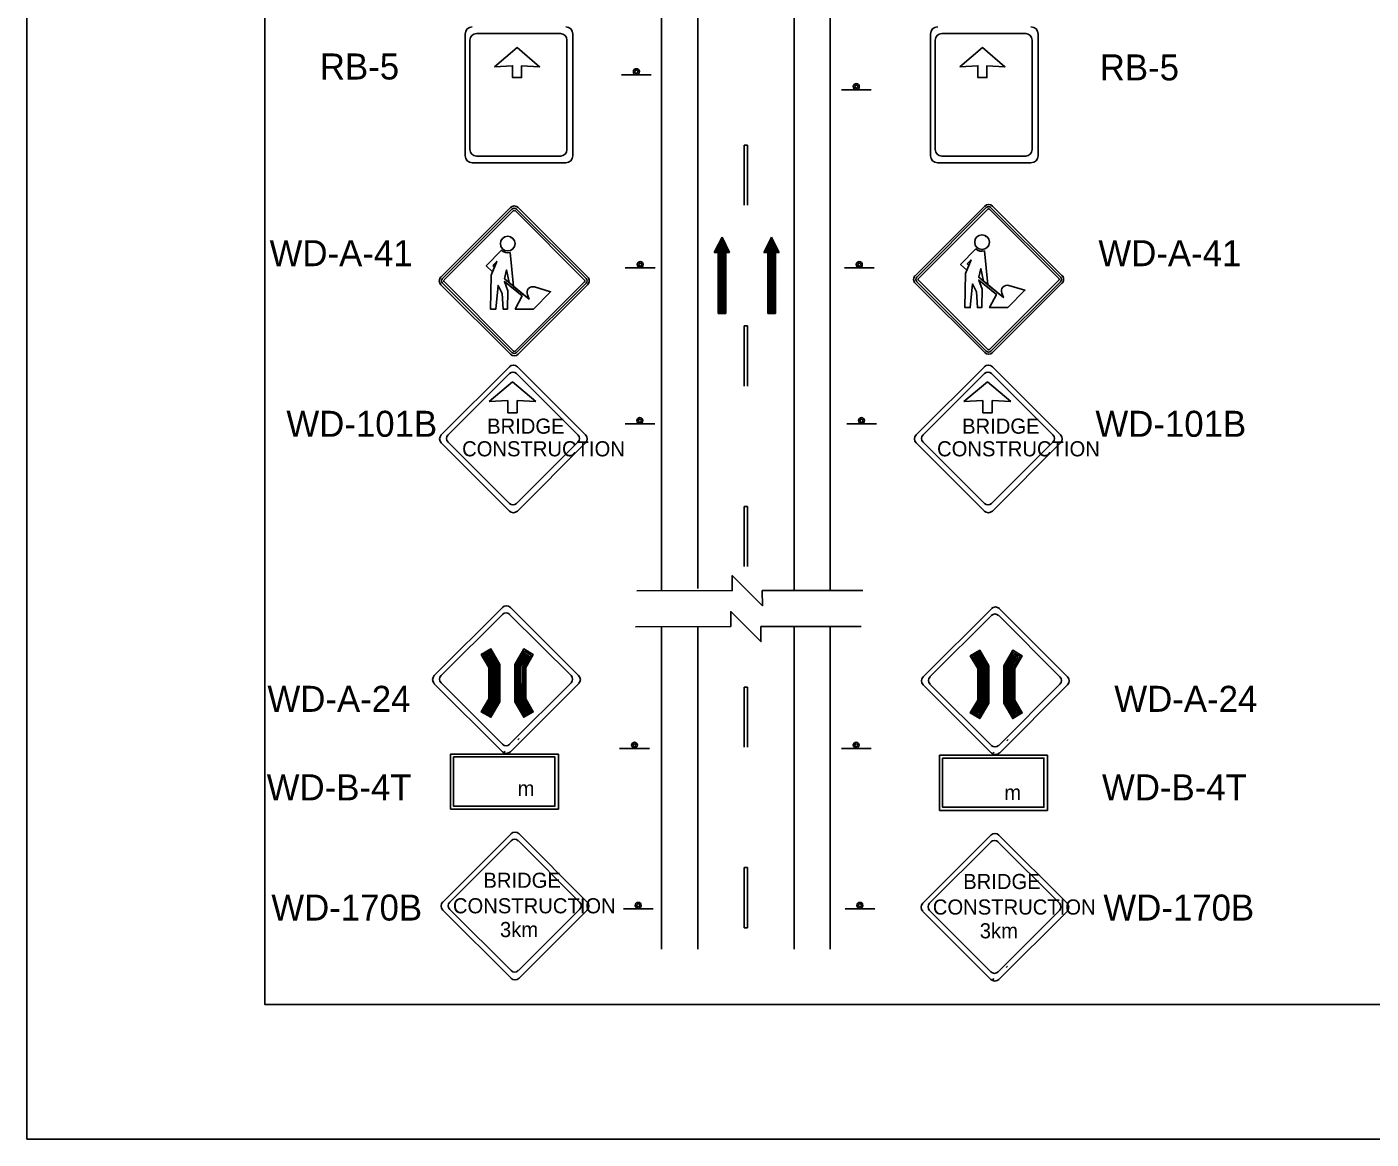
# Model space of a CAD drawing. Extents: x 2170 to 2386, y 134 to 413.
# Drawn here: x 2169.6 to 2277.6, y 133.8 to 223.1 of the extents above; entities that cross this region are included whole.
import ezdxf

# ---------------------------------------------------------------- set-up
doc = ezdxf.new("R2010")
doc.units = 0
for name, color, linetype in [('Level 1', 7, 'Continuous'), ('Level 10', 7, 'Continuous'), ('Level 2', 7, 'Continuous'), ('Level 20', 7, 'Continuous'), ('Level 44', 7, 'Continuous'), ('Level 60', 7, 'Continuous')]:
    doc.layers.add(name, color=color, linetype=linetype)

# ---------------------------------------------------------------- blocks, each defined once
blk = doc.blocks.new('2_95')
at = {"layer": 'Level 1'}
for points in [[(18.2, 120), (22.8, 116.1), (17.3, 102.4), (0, 118.7), (41.6, 161.6)], [(18.2, 120), (22.8, 116.1), (17.3, 102.4), (0, 118.7), (41.6, 161.6)], [(32.4, 65), (26.3, 0), (11.7, 0), (13.7, 93.4), (17.3, 102.4), (0, 118.7), (41.6, 161.6)], [(65.4, 155.5), (75, 62.5), (62.7, 72.8), (55.6, 107.4), (49.8, 83.3), (117.8, 27.3), (113.1, 39.4)], [(65.4, 155.5), (75, 62.5), (62.7, 72.8), (55.6, 107.4), (49.8, 83.3), (117.8, 27.3), (113.1, 39.4)], [(65.4, 155.5), (75, 62.5), (117.8, 27.3), (113.1, 39.4)], [(132.9, 60.9), (176.6, 47.8), (129.3, 0), (79.5, 0), (98.2, 36), (49.8, 75.6), (59.3, 50.4), (58.1, 0), (46.2, 0), (44, 43), (32.4, 65), (26.3, 0), (11.7, 0), (13.7, 93.4), (28.7, 130.9), (18.2, 120)], [(132.9, 60.9), (176.6, 47.8), (129.3, 0), (79.5, 0), (98.2, 36), (49.8, 75.6), (59.3, 50.4), (58.1, 0), (46.2, 0), (44, 43), (32.4, 65), (26.3, 0), (11.7, 0), (13.7, 93.4), (28.7, 130.9), (18.2, 120)], [(132.9, 60.9), (176.6, 47.8), (129.3, 0), (79.5, 0), (98.2, 36), (49.8, 75.6), (59.3, 50.4), (58.1, 0), (46.2, 0), (44, 43), (32.4, 65)]]:
    blk.add_lwpolyline(points, dxfattribs=at)
for points in [[(18.2, 120), (22.8, 116.1), (28.7, 130.9)], [(62.7, 72.7), (55.6, 107.4), (49.8, 83.3)]]:
    blk.add_lwpolyline(points, close=True, dxfattribs=at)
blk.add_circle((58.9, 179.8), 20.2, dxfattribs=at)
blk.add_circle((58.9, 179.8), 20.2, dxfattribs=at)
blk.add_circle((58.9, 179.8), 20.2, dxfattribs=at)
for centre, radius, start, end in [((58.9, 179.8), 25.1, 226.3135, 284.9576), ((58.9, 179.8), 25.1, 226.3135, 284.9576), ((58.9, 179.8), 25.1, 226.3135, 284.9576), ((128.2, 45.3), 16.3, 73.381, 201.0999), ((128.2, 45.3), 16.3, 73.381, 201.0999), ((128.2, 45.3), 16.3, 73.381, 201.0999)]:
    blk.add_arc(centre, radius, start, end, dxfattribs=at)
blk = doc.blocks.new('WDA41')
at = {"layer": 'Level 1'}
for p, q in [((-6.55, 0.35), (-0.35, 6.54)), ((-6.41, 0.21), (-0.21, 6.4)), ((-6.27, 0.07), (-0.08, 6.27)), ((0.07, 6.27), (6.27, 0.08)), ((0.21, 6.41), (6.41, 0.21)), ((0.35, 6.54), (6.54, 0.35)), ((0.29, 3.83), (0.3, 3.83)), ((-0.35, -6.54), (-6.55, -0.35)), ((-0.21, -6.4), (-6.41, -0.21)), ((-0.07, -6.27), (-6.27, -0.08)), ((6.27, -0.07), (0.08, -6.27)), ((6.41, -0.21), (0.21, -6.4)), ((6.55, -0.35), (0.35, -6.54))]:
    blk.add_line(p, q, dxfattribs=at)
for centre, radius, start, end in [((0, 6.19), 0.495, 45.0349, 135), ((0, 6.19), 0.3, 45.0349, 135), ((0, 6.19), 0.105, 45.0349, 135), ((-6.2, 0), 0.495, 135, 225.0349), ((-6.2, 0), 0.3, 135, 225.0349), ((-6.2, 0), 0.105, 135, 225.0349), ((6.2, 0), 0.105, 315, 45.035), ((6.2, 0), 0.3, 315, 45.035), ((6.2, 0), 0.495, 315, 45.035), ((0, -6.19), 0.495, 225.0348, 315), ((0, -6.19), 0.3, 225.0348, 315), ((0, -6.19), 0.105, 225.0348, 315)]:
    blk.add_arc(centre, radius, start, end, dxfattribs=at)
at = {"layer": 'Level 1', "xscale": 0.032498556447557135, "yscale": -0.032498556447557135, "rotation": 180}
blk.add_blockref('2_95', (2.5, -2.52), dxfattribs=at)

msp = doc.modelspace()

# ---------------------------------------------------------------- linework, layer by layer
at = {"layer": 'Level 10'}
for p, q in [((2223.52, 177.99), (2223.52, 287.5)), ((2231.26, 177.84), (2231.26, 287.27)), ((2225.47, 206.23), (2224.85, 205)), ((2225.01, 205.31), (2225.01, 205)), ((2225.08, 205.46), (2225.08, 205)), ((2225.16, 205.62), (2225.16, 200.09)), ((2225.24, 205.77), (2225.24, 200.09)), ((2225.31, 205.92), (2225.31, 200.09)), ((2225.39, 206.08), (2225.39, 200.09)), ((2225.47, 206.23), (2225.47, 200.09)), ((2225.47, 206.23), (2226.08, 205)), ((2225.54, 206.08), (2225.54, 200.09)), ((2225.62, 205.92), (2225.62, 200.09)), ((2225.7, 205.77), (2225.7, 200.09)), ((2225.77, 205.62), (2225.77, 200.09)), ((2225.85, 205.46), (2225.85, 205)), ((2225.93, 205.31), (2225.93, 205)), ((2229.45, 206.23), (2228.84, 205)), ((2228.99, 205.31), (2228.99, 205)), ((2229.07, 205.46), (2229.07, 205)), ((2229.14, 205.62), (2229.14, 200.09)), ((2229.22, 205.77), (2229.22, 200.09)), ((2229.3, 205.92), (2229.3, 200.09)), ((2229.38, 206.08), (2229.38, 200.09)), ((2229.45, 206.23), (2229.45, 200.09)), ((2229.45, 206.23), (2230.06, 205)), ((2229.53, 206.08), (2229.53, 200.09)), ((2229.6, 205.92), (2229.6, 200.09)), ((2229.68, 205.77), (2229.68, 200.09)), ((2229.76, 205.62), (2229.76, 200.09)), ((2229.83, 205.46), (2229.83, 205)), ((2229.91, 205.31), (2229.91, 205)), ((2224.85, 205), (2225.16, 205)), ((2224.93, 205.16), (2224.93, 205)), ((2225.16, 205), (2225.16, 200.09)), ((2225.77, 205), (2225.77, 200.09)), ((2225.77, 205), (2226.08, 205)), ((2226, 205.16), (2226, 205)), ((2228.84, 205), (2229.14, 205)), ((2228.91, 205.16), (2228.91, 205)), ((2229.14, 205), (2229.14, 200.09)), ((2229.76, 205), (2229.76, 200.09)), ((2229.76, 205), (2230.06, 205)), ((2229.99, 205.16), (2229.99, 205)), ((2225.16, 200.09), (2225.77, 200.09)), ((2229.14, 200.09), (2229.76, 200.09)), ((2223.52, 149.02), (2223.52, 174.93)), ((2231.26, 149.02), (2231.26, 174.95))]:
    msp.add_line(p, q, dxfattribs=at)
for points in [[(2203.91, 164.47), (2212.05, 164.47), (2212.05, 160.51), (2203.91, 160.51)], [(2243.19, 164.37), (2251.34, 164.37), (2251.34, 160.42), (2243.19, 160.42)]]:
    msp.add_lwpolyline(points, close=True, dxfattribs=at)
at = {"layer": 'Level 2'}
for p, q in [((2227.24, 213.62), (2227.24, 208.79)), ((2227.53, 213.62), (2227.24, 213.62)), ((2227.53, 208.79), (2227.53, 213.62)), ((2227.24, 199.11), (2227.24, 194.27)), ((2227.53, 199.11), (2227.24, 199.11)), ((2227.53, 194.27), (2227.53, 199.11)), ((2227.24, 184.6), (2227.24, 179.76)), ((2227.53, 184.6), (2227.24, 184.6)), ((2227.53, 179.76), (2227.53, 184.6)), ((2227.24, 170.08), (2227.24, 165.24)), ((2227.53, 170.08), (2227.24, 170.08)), ((2227.53, 165.24), (2227.53, 170.08)), ((2209.17, 165.95), (2209.07, 165.85)), ((2248.45, 165.86), (2248.35, 165.75)), ((2208.05, 164.94), (2207.95, 164.83)), ((2247.34, 164.84), (2247.23, 164.73)), ((2227.24, 155.57), (2227.24, 150.73)), ((2227.53, 155.57), (2227.24, 155.57)), ((2227.53, 150.73), (2227.53, 155.57)), ((2227.24, 150.73), (2227.53, 150.73)), ((2248.41, 147.66), (2248.31, 147.56)), ((2247.3, 146.65), (2247.2, 146.54))]:
    msp.add_line(p, q, dxfattribs=at)
at = {"layer": 'Level 20'}
for p, q in [((2234.16, 177.84), (2234.16, 321.3)), ((2220.62, 177.82), (2220.62, 313.63)), ((2220.62, 149.02), (2220.62, 174.93)), ((2234.16, 149.02), (2234.16, 174.95))]:
    msp.add_line(p, q, dxfattribs=at)
for points in [[(2218.63, 177.82), (2226.29, 177.83), (2226.29, 179.04), (2227.5, 177.83), (2228.72, 176.62), (2228.71, 177.83), (2236.79, 177.85)], [(2218.51, 174.93), (2226.17, 174.94), (2226.17, 176.15), (2227.38, 174.94), (2228.59, 173.73), (2228.59, 174.94), (2236.66, 174.96)]]:
    msp.add_lwpolyline(points, dxfattribs=at)
at = {"layer": 'Level 44'}
for p, q in [((2204.83, 212.78), (2204.83, 222.55)), ((2205.74, 222.59), (2212.49, 222.59)), ((2213.49, 222.55), (2213.49, 212.78)), ((2242.22, 212.78), (2242.22, 222.55)), ((2243.12, 222.59), (2249.87, 222.59)), ((2250.87, 222.55), (2250.87, 212.78)), ((2205.22, 213.27), (2205.22, 222.07)), ((2213.01, 222.07), (2213.01, 213.27)), ((2242.6, 213.27), (2242.6, 222.07)), ((2250.39, 222.07), (2250.39, 213.27)), ((2219.79, 219.27), (2217.4, 219.27)), ((2237.46, 218.07), (2235.07, 218.07)), ((2204.83, 212.78), (2204.83, 212.78)), ((2205.22, 213.27), (2205.22, 213.27)), ((2242.22, 212.78), (2242.22, 212.78)), ((2242.6, 213.27), (2242.6, 213.27)), ((2212.91, 212.2), (2205.41, 212.2)), ((2212.49, 212.75), (2205.74, 212.75)), ((2250.29, 212.2), (2242.79, 212.2)), ((2249.87, 212.75), (2243.12, 212.75)), ((2217.69, 203.76), (2220.09, 203.76)), ((2235.3, 203.76), (2237.69, 203.76)), ((2208.39, 195.82), (2202.91, 190.35)), ((2214.5, 190.35), (2209.03, 195.82)), ((2246.55, 195.82), (2241.07, 190.35)), ((2252.67, 190.35), (2247.2, 195.82)), ((2203.46, 190.34), (2208.39, 195.27)), ((2208.63, 194.62), (2206.75, 193.04)), ((2210.51, 193.04), (2208.63, 194.62)), ((2208.97, 195.27), (2213.89, 190.34)), ((2241.62, 190.34), (2246.55, 195.27)), ((2246.79, 194.62), (2244.91, 193.04)), ((2248.67, 193.04), (2246.79, 194.62)), ((2247.13, 195.27), (2252.06, 190.34)), ((2206.75, 193.04), (2208.25, 193.12)), ((2208.25, 193.12), (2208.25, 192.11)), ((2209.01, 192.11), (2209.01, 193.12)), ((2209.01, 193.12), (2210.51, 193.04)), ((2244.91, 193.04), (2246.42, 193.12)), ((2246.42, 193.12), (2246.42, 192.11)), ((2247.17, 192.11), (2247.17, 193.12)), ((2247.17, 193.12), (2248.67, 193.04)), ((2208.25, 192.11), (2209, 192.11)), ((2220.07, 191.23), (2217.68, 191.23)), ((2237.89, 191.23), (2235.49, 191.23)), ((2246.42, 192.11), (2247.17, 192.11)), ((2202.91, 189.7), (2208.39, 184.22)), ((2202.91, 189.7), (2202.91, 189.7)), ((2208.39, 184.83), (2203.46, 189.76)), ((2213.89, 189.76), (2208.97, 184.83)), ((2209.03, 184.22), (2214.5, 189.7)), ((2241.07, 189.7), (2246.55, 184.22)), ((2241.08, 189.7), (2241.07, 189.7)), ((2246.55, 184.83), (2241.62, 189.76)), ((2252.06, 189.76), (2247.13, 184.83)), ((2247.2, 184.22), (2252.67, 189.7)), ((2207.83, 176.47), (2202.35, 171)), ((2213.95, 171), (2208.48, 176.47)), ((2247.11, 176.38), (2241.64, 170.91)), ((2253.23, 170.91), (2247.76, 176.38)), ((2202.9, 171), (2207.83, 175.92)), ((2208.41, 175.92), (2213.34, 171)), ((2242.18, 170.9), (2247.11, 175.83)), ((2247.7, 175.83), (2252.62, 170.9)), ((2202.35, 170.35), (2207.83, 164.88)), ((2202.36, 170.35), (2202.35, 170.35)), ((2207.83, 165.49), (2202.9, 170.42)), ((2213.34, 170.42), (2208.41, 165.49)), ((2208.48, 164.88), (2213.95, 170.35)), ((2241.64, 170.26), (2247.11, 164.78)), ((2241.64, 170.26), (2241.64, 170.26)), ((2247.11, 165.39), (2242.18, 170.32)), ((2252.62, 170.32), (2247.7, 165.39)), ((2247.76, 164.78), (2253.23, 170.26)), ((2219.64, 165.15), (2217.24, 165.15)), ((2237.46, 165.15), (2235.06, 165.15)), ((2208.52, 158.28), (2203.05, 152.81)), ((2203.59, 152.81), (2208.52, 157.73)), ((2209.11, 157.73), (2214.03, 152.81)), ((2214.64, 152.81), (2209.17, 158.28)), ((2247.07, 158.18), (2241.6, 152.71)), ((2253.19, 152.71), (2247.72, 158.18)), ((2242.14, 152.71), (2247.07, 157.63)), ((2247.66, 157.63), (2252.58, 152.71)), ((2203.05, 152.16), (2208.52, 146.69)), ((2203.05, 152.16), (2203.05, 152.16)), ((2208.52, 147.3), (2203.59, 152.22)), ((2214.03, 152.22), (2209.11, 147.3)), ((2209.17, 146.69), (2214.64, 152.16)), ((2219.94, 152.27), (2217.55, 152.27)), ((2237.76, 152.27), (2235.36, 152.27)), ((2241.6, 152.06), (2247.07, 146.59)), ((2241.6, 152.06), (2241.6, 152.06)), ((2247.07, 147.2), (2242.14, 152.12)), ((2252.58, 152.12), (2247.66, 147.2)), ((2247.72, 146.59), (2253.19, 152.06))]:
    msp.add_line(p, q, dxfattribs=at)
for points in [[(2207.2, 219.93), (2209.01, 221.46), (2210.82, 219.93), (2209.37, 220.01), (2209.37, 219.05), (2208.65, 219.05), (2208.65, 220.01)], [(2244.58, 219.93), (2246.39, 221.46), (2248.2, 219.93), (2246.76, 220.01), (2246.76, 219.05), (2246.03, 219.05), (2246.03, 220.01)], [(2212.33, 164.7), (2203.67, 164.7), (2203.67, 160.27), (2212.33, 160.27)], [(2251.61, 164.6), (2242.95, 164.6), (2242.95, 160.17), (2251.61, 160.17)]]:
    msp.add_lwpolyline(points, close=True, dxfattribs=at)
for points in [[(2206.13, 168.09), (2206.73, 169.13), (2206.73, 171.65), (2206.13, 172.69), (2206.9, 173.14), (2207.62, 171.89), (2207.62, 168.89), (2206.9, 167.65), (2206.13, 168.09), (2206.28, 168.13), (2206.84, 169.1), (2206.84, 171.68), (2206.28, 172.65), (2206.86, 172.99), (2207.51, 171.87), (2207.51, 168.92), (2206.86, 167.8), (2206.28, 168.13), (2206.43, 168.17), (2206.95, 169.07), (2206.95, 171.71), (2206.43, 172.61), (2206.82, 172.83), (2207.4, 171.83), (2207.4, 168.95), (2206.82, 167.95), (2206.43, 168.17), (2206.58, 168.21), (2207.07, 169.04), (2207.06, 171.74), (2206.58, 172.57), (2206.78, 172.69), (2207.29, 171.8), (2207.29, 168.98), (2206.77, 168.09), (2206.58, 168.21), (2206.73, 168.25), (2206.83, 168.2), (2206.73, 168.25), (2207.17, 169.01), (2207.18, 171.77), (2206.73, 172.53), (2206.83, 172.59), (2206.9, 173.14)], [(2209.54, 167.65), (2208.82, 168.89), (2208.82, 171.89), (2209.54, 173.14), (2210.31, 172.69), (2209.71, 171.65), (2209.71, 169.13), (2210.31, 168.09), (2209.54, 167.65), (2209.58, 167.82), (2208.95, 168.92), (2208.95, 171.85), (2209.59, 172.96), (2210.14, 172.64), (2209.58, 171.68), (2209.58, 169.1), (2210.14, 168.14), (2209.58, 167.82), (2209.63, 167.99), (2209.07, 168.96), (2209.07, 171.82), (2209.64, 172.78), (2209.96, 172.59), (2209.46, 171.72), (2209.46, 169.06), (2209.96, 168.19), (2209.63, 167.99), (2209.68, 168.17), (2209.21, 168.99), (2209.21, 171.78), (2209.68, 172.61), (2209.79, 172.55), (2209.32, 171.75), (2209.33, 169.03), (2209.79, 168.23), (2209.68, 168.17), (2210.31, 168.09)], [(2245.41, 168), (2246.02, 169.03), (2246.02, 171.56), (2245.41, 172.59), (2246.18, 173.04), (2246.91, 171.79), (2246.91, 168.8), (2246.18, 167.55), (2245.41, 168), (2245.56, 168.03), (2246.12, 169.01), (2246.13, 171.58), (2245.56, 172.55), (2246.14, 172.89), (2246.8, 171.77), (2246.8, 168.82), (2246.14, 167.7), (2245.56, 168.03), (2245.72, 168.08), (2246.23, 168.97), (2246.24, 171.61), (2245.72, 172.51), (2246.1, 172.73), (2246.68, 171.73), (2246.68, 168.85), (2246.1, 167.85), (2245.72, 168.08), (2245.86, 168.11), (2246.35, 168.94), (2246.34, 171.64), (2245.86, 172.47), (2246.06, 172.59), (2246.57, 171.71), (2246.57, 168.88), (2246.05, 168), (2245.86, 168.11), (2246.02, 168.16), (2246.12, 168.1), (2246.02, 168.16), (2246.45, 168.91), (2246.46, 171.67), (2246.02, 172.43), (2246.12, 172.49), (2246.18, 173.04)], [(2248.83, 167.55), (2248.11, 168.8), (2248.11, 171.79), (2248.83, 173.04), (2249.59, 172.59), (2248.99, 171.56), (2248.99, 169.03), (2249.59, 168), (2248.83, 167.55), (2248.87, 167.72), (2248.23, 168.83), (2248.24, 171.76), (2248.87, 172.86), (2249.42, 172.54), (2248.87, 171.58), (2248.86, 169), (2249.42, 168.04), (2248.87, 167.72), (2248.91, 167.9), (2248.36, 168.86), (2248.36, 171.72), (2248.92, 172.69), (2249.24, 172.5), (2248.74, 171.62), (2248.74, 168.97), (2249.24, 168.09), (2248.91, 167.9), (2248.96, 168.07), (2248.49, 168.9), (2248.49, 171.69), (2248.97, 172.51), (2249.07, 172.45), (2248.61, 171.65), (2248.61, 168.93), (2249.07, 168.13), (2248.96, 168.07), (2249.59, 168)]]:
    msp.add_lwpolyline(points, dxfattribs=at)
for centre, radius in [((2218.59, 219.53), 0.24), ((2218.59, 219.53), 0.12), ((2236.26, 218.33), 0.24), ((2236.26, 218.33), 0.12), ((2218.9, 204.03), 0.24), ((2218.9, 204.03), 0.12), ((2236.5, 204.03), 0.24), ((2236.5, 204.03), 0.12), ((2218.87, 191.49), 0.24), ((2218.87, 191.49), 0.12), ((2236.68, 191.49), 0.24), ((2236.68, 191.49), 0.12), ((2218.44, 165.41), 0.24), ((2218.44, 165.41), 0.12), ((2236.25, 165.41), 0.24), ((2236.25, 165.41), 0.12), ((2218.74, 152.54), 0.24), ((2218.74, 152.54), 0.12), ((2236.55, 152.54), 0.24), ((2236.55, 152.54), 0.12)]:
    msp.add_circle(centre, radius, dxfattribs=at)
for centre, radius, start, end in [((2205.41, 222.55), 0.578, 90, 180), ((2205.74, 222.07), 0.52, 90, 180), ((2212.49, 222.07), 0.52, 360, 90), ((2212.91, 222.55), 0.578, 360, 90), ((2242.8, 222.55), 0.578, 90, 180), ((2243.12, 222.07), 0.52, 90, 180), ((2249.87, 222.07), 0.52, 360, 90), ((2250.29, 222.55), 0.578, 360, 90), ((2205.41, 212.78), 0.578, 180, 270), ((2205.74, 213.27), 0.52, 180, 270), ((2212.49, 213.27), 0.52, 270, 360), ((2212.91, 212.78), 0.578, 270, 360), ((2242.8, 212.78), 0.578, 180, 270), ((2243.12, 213.27), 0.52, 180, 270), ((2249.87, 213.27), 0.52, 270, 360), ((2250.29, 212.78), 0.578, 270, 360), ((2208.71, 195.5), 0.458, 45, 135), ((2246.87, 195.5), 0.458, 45, 135), ((2208.68, 194.98), 0.412, 45, 135), ((2246.84, 194.98), 0.412, 45, 135), ((2203.24, 190.02), 0.458, 135, 225), ((2203.75, 190.05), 0.412, 135, 225), ((2213.6, 190.05), 0.412, 315, 45), ((2214.18, 190.02), 0.458, 315, 45), ((2241.4, 190.02), 0.458, 135, 225), ((2241.92, 190.05), 0.412, 135, 225), ((2251.77, 190.05), 0.412, 315, 45), ((2252.35, 190.02), 0.458, 315, 45), ((2208.68, 185.13), 0.412, 225, 315), ((2246.84, 185.13), 0.412, 225, 315), ((2208.71, 184.55), 0.458, 225, 315), ((2246.87, 184.55), 0.458, 225, 315), ((2208.15, 176.15), 0.458, 45, 135), ((2208.12, 175.63), 0.412, 45, 135), ((2247.44, 176.06), 0.458, 45, 135), ((2247.4, 175.54), 0.412, 45, 135), ((2202.68, 170.68), 0.458, 135, 225), ((2203.19, 170.71), 0.412, 135, 225), ((2213.05, 170.71), 0.412, 315, 45), ((2213.63, 170.68), 0.458, 315, 45), ((2241.96, 170.58), 0.458, 135, 225), ((2242.48, 170.61), 0.412, 135, 225), ((2252.33, 170.61), 0.412, 315, 45), ((2252.91, 170.58), 0.458, 315, 45), ((2208.12, 165.78), 0.412, 225, 315), ((2247.4, 165.69), 0.412, 225, 315), ((2208.15, 165.21), 0.458, 225, 315), ((2247.44, 165.11), 0.458, 225, 315), ((2208.84, 157.96), 0.458, 45, 135), ((2208.81, 157.44), 0.412, 45, 135), ((2247.4, 157.86), 0.458, 45, 135), ((2247.36, 157.34), 0.412, 45, 135), ((2203.37, 152.49), 0.458, 135, 225), ((2203.89, 152.51), 0.412, 135, 225), ((2213.74, 152.51), 0.412, 315, 45), ((2214.32, 152.49), 0.458, 315, 45), ((2241.92, 152.39), 0.458, 135, 225), ((2242.44, 152.42), 0.412, 135, 225), ((2252.29, 152.42), 0.412, 315, 45), ((2252.87, 152.39), 0.458, 315, 45), ((2208.81, 147.59), 0.412, 225, 315), ((2247.36, 147.49), 0.412, 225, 315), ((2208.84, 147.01), 0.458, 225, 315), ((2247.4, 146.92), 0.458, 225, 315)]:
    msp.add_arc(centre, radius, start, end, dxfattribs=at)
at = {"layer": 'Level 60'}
for points in [[(2169.62, 412.76), (2385.62, 412.76), (2385.62, 133.76), (2169.62, 133.76)], [(2188.75, 401.95), (2375.62, 401.95), (2375.62, 144.57), (2188.75, 144.57)]]:
    msp.add_lwpolyline(points, close=True, dxfattribs=at)

# ---------------------------------------------------------------- block references
at = {"layer": 'Level 1', "xscale": 0.9, "yscale": -0.9, "rotation": 180}
for p in [(2208.78, 202.72), (2246.89, 202.84)]:
    msp.add_blockref('WDA41', p, dxfattribs=at)

# ---------------------------------------------------------------- texts
at = {"layer": 'Level 1'}
for p in [(2188.89, 160.98), (2256, 160.98)]:
    msp.add_text('WD-B-4T', height=2.09, dxfattribs=at).set_placement(p)
at = {"layer": 'Level 10'}
for s, p in [('RB-5', (2193.16, 218.9)), ('RB-5', (2255.82, 218.83)), ('WD-A-41', (2189.12, 203.9)), ('WD-A-41', (2255.71, 203.9)), ('WD-101B', (2190.47, 190.19)), ('WD-101B', (2255.47, 190.19)), ('WD-A-24', (2188.95, 168.09)), ('WD-A-24', (2256.99, 168.09)), ('WD-170B', (2189.26, 151.32)), ('WD-170B', (2256.11, 151.32))]:
    msp.add_text(s, height=2.09, dxfattribs=at).set_placement(p)
at = {"layer": 'Level 44'}
for s, p in [('BRIDGE', (2206.6, 190.44)), ('BRIDGE', (2244.76, 190.44)), ('CONSTRUCTION', (2204.59, 188.62)), ('CONSTRUCTION', (2242.75, 188.62)), ('BRIDGE', (2206.3, 153.95)), ('BRIDGE', (2244.85, 153.85))]:
    msp.add_text(s, height=1.214, rotation=360, dxfattribs=at).set_placement(p)
for s, height, p in [('m', 1.21, (2209.05, 161.33)), ('m', 1.21, (2248.15, 161)), ('CONSTRUCTION', 1.2143, (2203.85, 151.9)), ('CONSTRUCTION', 1.2143, (2242.41, 151.8)), ('3km', 1.214, (2207.63, 149.99)), ('3km', 1.214, (2246.18, 149.89))]:
    msp.add_text(s, height=height, dxfattribs=at).set_placement(p)

doc.saveas('drawing.dxf')
